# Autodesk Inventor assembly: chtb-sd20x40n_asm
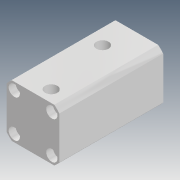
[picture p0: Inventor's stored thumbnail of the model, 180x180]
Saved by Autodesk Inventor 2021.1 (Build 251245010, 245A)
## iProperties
Company: Microsoft
Created: 2018-04
Part Number: chtb-sd20x40n_asm
Description: STEP AP214
Document SubType Name: Assembly
Designer: user
Title: chtb-sd20x40n_asm.STEP
Author: Windows
Revision Number: ÈÎºÎ
Sending System: SolidWorks 2015
Preprocessor: SwSTEP 2.0
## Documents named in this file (4)
- D:\Vault_2016\Projekty\Clamptek\Hydraulic\CHTB\CHTB-20\Inventor\CHTB-SD20x40N\chtb-sd20x40n_asm.iam
- D:\Vault_2016\Projekty\Clamptek\Hydraulic\CHTB\CHTB-20\Inventor\CHTB-SD20x40N\CHTB-SD20X40NBT.ipt
- D:\Vault_2016\Projekty\Clamptek\Hydraulic\CHTB\CHTB-20\Inventor\CHTB-SD20x40N\CHTB-SD20X40NHSG.ipt
- D:\Vault_2016\Projekty\Clamptek\Hydraulic\CHTB\CHTB-20\Inventor\CHTB-SD20x40N\QG.ipt
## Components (3 placed, 3 different names)
1. CHTB-SD20X40NBT_1
2. CHTB-SD20X40NHSG_2
3. QG_3
